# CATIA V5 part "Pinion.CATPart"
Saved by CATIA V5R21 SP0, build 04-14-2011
Part number: Part3
Bounding box of the stored display mesh (mm): x -50 to 70, y -20 to 20, z -20 to 20
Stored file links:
  D:\CATIA V5R21 E-RESOURCES\CATIA-V5R21\catia-v5r21-Prts\c16_catia_v5r21_prt\Rack Joint(Fig16-57)\Pinion.CATPart
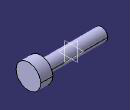
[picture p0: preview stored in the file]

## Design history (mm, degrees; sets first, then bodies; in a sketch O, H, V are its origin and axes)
Body1 (main body)
  Sketch1 on yz-plane, origin (0, 0, 0), H (0, 1, 0), V (0, 0, 1)
    reference intersected line E1 through (0, 0) direction (-1, 0) from xy-plane
    reference intersected line E3 through (0, 0) direction (0, 1) from zx-plane
    reference intersected line E4 through (0, 0) direction (-1, 0) from xy-plane
    reference intersected line E6 through (0, 0) direction (0, 1) from zx-plane
    reference intersected line E7 through (0, 0) direction (-1, 0) from xy-plane
    reference intersected line E9 through (0, 0) direction (0, 1) from zx-plane
    circle A1 centre (0, 0) radius 10
    radius A1 = 10
    vertical: E3 V, E6 V, E9 V
    horizontal: E1 H, E4 H, E7 H
  Pad1: profile Sketch1, direction (1, 0, 0), length 50, mirrored extent
  Sketch2 on end face of Pad1, origin (50, 0, 0), H (0, 1, 0), V (0, 0, 1)
    circle A1 centre (0, 0) radius 20
    radius A1 = 20
  Pad2: profile Sketch2, direction (1, 0, 0), length 20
